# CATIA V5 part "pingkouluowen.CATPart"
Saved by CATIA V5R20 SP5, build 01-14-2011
Part number: Part1
Bounding box of the stored display mesh (mm): x -16 to 15.999, y -15.984 to 15.984, z 0 to 20
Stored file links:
  E:\scc\pingkouluowen.CATPart
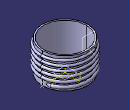
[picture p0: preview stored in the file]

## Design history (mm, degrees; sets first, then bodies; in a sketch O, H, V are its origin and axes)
Body1 (main body)
  Sketch1 on xy-plane, origin (0, 0, 0), H (1, 0, 0), V (0, 1, 0)
    circle A1 centre (0, 0) radius 15
    point P1 (15, 0)
    radius A1 = 15
    coincidence: A1 P1, P1 H
  Pad1: profile Sketch1, direction (0, 0, 1), length 20, thin wall 1
  Sketch2 on xy-plane, origin (0, 0, 0), H (1, 0, 0), V (0, 1, 0)
    point P1 (15, 0)
    distance P1 O = 15
    coincidence: P1 H
  Plane1: type Offset, RefPlane xy-plane, Offset 2
  Sketch3 on Plane1, origin (0, 0, 2), H (1, 0, 0), V (0, 1, 0)
    point P1 (15, 0)
    distance P1 O = 15
    coincidence: P1 H
  Helix1: Direction Z axis, RefPoint Sketch3, Pitch 3, Height 16, TaperAngle 0
  Line1: type PtDir, RefPoint Sketch3, Direction (1, 0, 0), Start 0, End 5
  Point1: type OnCurve, Support Helix1, RefPoint vertex of Helix1, Length -5
  Line2: type PtDir, RefPoint vertex of Helix1, Direction (0, 1, 0), Start 0, End 5
  Connect1: Curve1 Line2, Point1 vertex of Line2, Tension1 1, Curve2 Helix1, Point2 Point1, Tension2 1
  Point2: type OnCurve, Support Line1, Length 5
  Point3: type OnCurve, Support Connect1, RefPoint Point2, Length -5
  Connect2: Curve1 Line1, Point1 vertex of Line1, Tension1 1, Curve2 Connect1, Point2 Point3, Tension2 1
  Plane2: type Normal, Curve Connect2, RefPoint vertex of Connect1
  Circle1: type CtrRad, Start 0, End 180, Radius 1, Center vertex of Connect1, Support Plane2, FirstDirection (1, 0, 0)
  Rib1: profile Circle1, centre curve Connect2
  Sketch4 on xy-plane, origin (0, 0, 0), H (1, 0, 0), V (0, 1, 0)
    circle A1 centre (0, 0) radius 14
    radius A1 = 14
  Pocket1: profile Sketch4, direction (0, 0, 1), length 20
